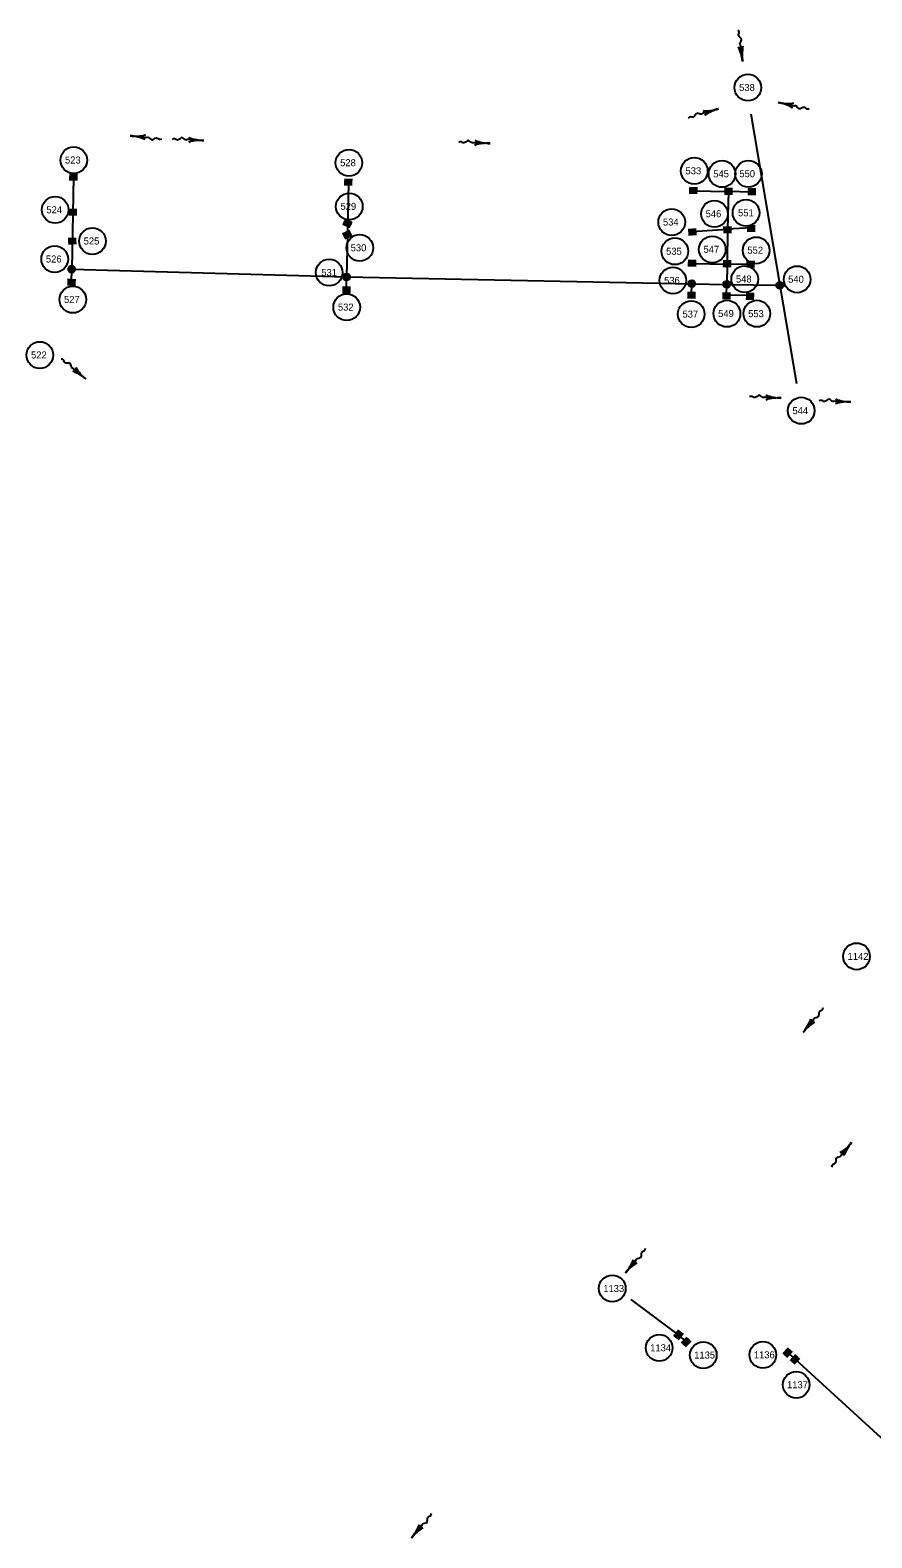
# Model space of a CAD drawing. Extents: x 594534 to 598564, y 225861 to 236229.
# Drawn here: x 595247 to 595967, y 230002 to 231290 of the extents above; entities that cross this region are included whole.
import ezdxf

# ---------------------------------------------------------------- set-up
doc = ezdxf.new("R2010")
doc.units = 0
for name, color, linetype in [('P_DRN_Flow', 7, 'Continuous'), ('P_DRN_Inlet', 7, 'Continuous'), ('P_DRN_SS_MH', 7, 'Continuous'), ('P_DRN_SS_UG', 7, 'Continuous'), ('P_DRN_Text', 7, 'Continuous')]:
    doc.layers.add(name, color=color, linetype=linetype)

msp = doc.modelspace()

# ---------------------------------------------------------------- linework, layer by layer
at = {"layer": 'P_DRN_Flow'}
for p, q in [((595856.3, 231263.7), (595854.4, 231277.7)), ((595886.7, 231228.6), (595900.6, 231225.8)), ((595835.6, 231223.2), (595822.1, 231219.1)), ((595332.9, 231200.1), (595347, 231198.6)), ((595395.8, 231196.1), (595381.7, 231196.8)), ((595640.4, 231193.6), (595626.3, 231194.2)), ((595295, 230992.3), (595284.1, 231001.3)), ((595889.1, 230976), (595875, 230976.6)), ((595948.6, 230972.6), (595934.5, 230973.2)), ((595908.1, 230434.1), (595917.1, 230444.9)), ((595949.5, 230339.6), (595940.4, 230328.8)), ((595756.3, 230228.4), (595765.3, 230239.2)), ((595573.3, 230001.9), (595582.4, 230012.7))]:
    msp.add_line(p, q, dxfattribs=at)
for points in [[(595852.6, 231276.1), (595855, 231273.2), (595856.6, 231276.6)], [(595899.7, 231228), (595896.1, 231226.7), (595898.9, 231224.1)], [(595823.9, 231217.6), (595826.4, 231220.4), (595822.7, 231221.4)], [(595345.9, 231200.8), (595342.5, 231199.1), (595345.5, 231196.8)], [(595382.9, 231194.7), (595386.2, 231196.5), (595383.1, 231198.7)], [(595627.5, 231192.2), (595630.8, 231194), (595627.7, 231196.2)], [(595283.8, 230998.9), (595287.6, 230998.4), (595286.4, 231002)], [(595876.3, 230974.5), (595879.6, 230976.4), (595876.4, 230978.5)], [(595935.8, 230971.2), (595939.1, 230973), (595935.9, 230975.2)], [(595914.8, 230445.2), (595914.2, 230441.5), (595917.8, 230442.6)], [(595942.8, 230328.5), (595943.3, 230332.2), (595939.7, 230331.1)], [(595762.9, 230239.5), (595762.4, 230235.8), (595766, 230236.9)], [(595580, 230012.9), (595579.4, 230009.2), (595583, 230010.4)]]:
    msp.add_lwpolyline(points, dxfattribs=at)
for centre, start, end in [((595814.7, 231258.1), 7.5832, 25.3455), ((595897.9, 231269.2), 169.8209, 187.5832), ((595895.2, 231269.7), 258.3474, 276.1098), ((595878.2, 231187.5), 60.5851, 78.3474), ((595823.3, 231263.3), 269.2685, 287.0308), ((595847.9, 231183.1), 107.0308, 124.7931), ((595337.3, 231241.8), 263.9732, 281.7355), ((595328.5, 231158.4), 66.2108, 83.9732), ((595393.9, 231154.2), 87.4555, 105.2178), ((595397.7, 231238), 249.6932, 267.4555), ((595638.5, 231151.7), 87.4555, 105.2178), ((595642.3, 231235.5), 249.6932, 267.4555), ((595268.3, 230959.9), 50.543, 68.3053), ((595321.6, 231024.7), 212.7806, 230.543), ((595887.3, 230934.1), 87.4555, 105.2178), ((595891, 231017.9), 249.6932, 267.4555), ((595946.8, 230930.7), 87.4555, 105.2178), ((595950.5, 231014.5), 249.6932, 267.4555), ((595875.9, 230461), 320.0425, 337.8048), ((595940.2, 230407.1), 122.2801, 140.0425), ((595917.4, 230366.6), 302.1583, 319.9206), ((595981.6, 230312.6), 139.9206, 157.6829), ((595724.1, 230255.3), 320.0425, 337.8048), ((595788.4, 230201.5), 122.2801, 140.0425), ((595541.1, 230028.8), 320.0425, 337.8048), ((595605.4, 229974.9), 122.2801, 140.0425)]:
    msp.add_arc(centre, 42, start, end, dxfattribs=at)
for points in [[(595854.4, 231277.7), (595854, 231278.4), (595855.4, 231282.2), (595852.7, 231285.8), (595853.3, 231288.8), (595852.4, 231290.4)], [(595822.1, 231219.1), (595821.4, 231218.6), (595817.4, 231219.3), (595814.3, 231216.1), (595811.3, 231216.1), (595809.8, 231215)], [(595900.6, 231225.8), (595901.4, 231225.9), (595904.5, 231223.3), (595908.8, 231224.7), (595911.4, 231223.2), (595913.2, 231223.5)], [(595347, 231198.6), (595347.8, 231198.9), (595351.2, 231196.6), (595355.3, 231198.4), (595358, 231197.2), (595359.8, 231197.6)], [(595381.7, 231196.8), (595380.9, 231196.5), (595377.4, 231198.5), (595373.4, 231196.5), (595370.6, 231197.6), (595368.8, 231197)], [(595626.3, 231194.2), (595625.5, 231194), (595622, 231196), (595617.9, 231194), (595615.2, 231195), (595613.4, 231194.5)], [(595284.1, 231001.3), (595283.3, 231001.6), (595281.7, 231005.3), (595277.2, 231006.1), (595275.7, 231008.6), (595273.9, 231009.3)], [(595875, 230976.6), (595874.2, 230976.3), (595870.7, 230978.4), (595866.7, 230976.3), (595863.9, 230977.4), (595862.2, 230976.9)], [(595934.5, 230973.2), (595933.7, 230973), (595930.2, 230975), (595926.2, 230973), (595923.4, 230974), (595921.7, 230973.5)], [(595917.1, 230444.9), (595917.4, 230445.7), (595921.2, 230447.3), (595922, 230451.7), (595924.5, 230453.3), (595925.2, 230455)], [(595940.4, 230328.8), (595940.1, 230328), (595936.3, 230326.4), (595935.5, 230322), (595932.9, 230320.4), (595932.3, 230318.7)], [(595765.3, 230239.2), (595765.6, 230240), (595769.4, 230241.6), (595770.2, 230246), (595772.7, 230247.6), (595773.4, 230249.3)], [(595582.4, 230012.7), (595582.6, 230013.5), (595586.4, 230015), (595587.2, 230019.5), (595589.7, 230021), (595590.4, 230022.8)]]:
    msp.add_spline(points, degree=3, dxfattribs=at)
at = {"layer": 'P_DRN_Inlet'}
for p, q in [((595280.8, 231164.6), (595287.7, 231164.5)), ((595280.8, 231163.7), (595287.7, 231163.6)), ((595280.8, 231162.8), (595287.7, 231162.7)), ((595280.9, 231167.3), (595287.8, 231167.2)), ((595280.9, 231166.4), (595287.7, 231166.3)), ((595280.9, 231165.5), (595287.7, 231165.4)), ((595522.8, 231162.6), (595515.9, 231162.8)), ((595522.7, 231161.7), (595515.9, 231161.9)), ((595522.7, 231160.8), (595515.8, 231161)), ((595522.7, 231159.9), (595515.8, 231160.1)), ((595522.7, 231159), (595515.8, 231159.2)), ((595522.7, 231158.1), (595515.8, 231158.3)), ((595810.6, 231151.3), (595817.5, 231151.1)), ((595810.7, 231154.9), (595817.6, 231154.7)), ((595810.7, 231154), (595817.6, 231153.8)), ((595810.7, 231153.1), (595817.6, 231152.9)), ((595810.7, 231152.2), (595817.5, 231152)), ((595810.8, 231155.8), (595817.6, 231155.6)), ((595840.7, 231155.1), (595847.6, 231155.1)), ((595840.7, 231154.2), (595847.6, 231154.2)), ((595840.7, 231153.3), (595847.6, 231153.3)), ((595840.7, 231152.4), (595847.6, 231152.4)), ((595840.7, 231151.5), (595847.6, 231151.5)), ((595840.7, 231150.6), (595847.6, 231150.6)), ((595860.7, 231153), (595867.6, 231152.9)), ((595860.7, 231152.1), (595867.6, 231152)), ((595860.7, 231151.2), (595867.6, 231151.1)), ((595860.7, 231150.3), (595867.5, 231150.2)), ((595860.8, 231154.8), (595867.7, 231154.7)), ((595860.8, 231153.9), (595867.6, 231153.8)), ((595280.3, 231136.4), (595287.2, 231136.3)), ((595280.4, 231137.3), (595287.2, 231137.2)), ((595280.3, 231135.5), (595287.2, 231135.4)), ((595280.3, 231134.6), (595287.2, 231134.5)), ((595280.3, 231133.7), (595287.2, 231133.6)), ((595280.3, 231132.8), (595287.2, 231132.7)), ((595520.7, 231121.7), (595514.5, 231124.7)), ((595521.1, 231122.5), (595514.9, 231125.5)), ((595521.5, 231123.3), (595515.3, 231126.3)), ((595521.9, 231124.1), (595515.7, 231127.1)), ((595522.3, 231124.9), (595516.1, 231128)), ((595522.7, 231125.7), (595516.5, 231128.8)), ((595860.2, 231123.3), (595867.1, 231123.2)), ((595279.8, 231112.3), (595286.6, 231112.7)), ((595279.8, 231111.4), (595286.7, 231111.8)), ((595279.9, 231110.5), (595286.7, 231110.9)), ((595514.4, 231116.2), (595520.7, 231119.1)), ((595514.8, 231115.4), (595521, 231118.3)), ((595515.2, 231114.6), (595521.4, 231117.5)), ((595515.5, 231113.8), (595521.8, 231116.7)), ((595515.9, 231113), (595522.2, 231115.8)), ((595516.3, 231112.2), (595522.5, 231115)), ((595809.8, 231120), (595816.6, 231120.5)), ((595809.8, 231119.1), (595816.7, 231119.6)), ((595809.9, 231118.2), (595816.8, 231118.7)), ((595810, 231117.3), (595816.8, 231117.8)), ((595810, 231116.4), (595816.9, 231116.9)), ((595810.1, 231115.5), (595817, 231116)), ((595839.8, 231121.9), (595846.7, 231122.2)), ((595839.9, 231121), (595846.8, 231121.3)), ((595839.9, 231120.1), (595846.8, 231120.4)), ((595840, 231119.2), (595846.8, 231119.5)), ((595840, 231118.3), (595846.9, 231118.6)), ((595840.1, 231117.4), (595846.9, 231117.7)), ((595860.1, 231118.8), (595867, 231118.7)), ((595860.2, 231122.4), (595867.1, 231122.3)), ((595860.2, 231121.5), (595867.1, 231121.4)), ((595860.2, 231120.6), (595867.1, 231120.5)), ((595860.2, 231119.7), (595867, 231119.6)), ((595279.9, 231109.6), (595286.8, 231110)), ((595280, 231108.7), (595286.8, 231109.1)), ((595280, 231107.8), (595286.9, 231108.2)), ((595809.6, 231091.1), (595816.5, 231090.9)), ((595809.6, 231090.2), (595816.5, 231090)), ((595809.6, 231089.3), (595816.5, 231089.1)), ((595809.7, 231093.8), (595816.6, 231093.6)), ((595809.7, 231092.9), (595816.6, 231092.7)), ((595809.7, 231092), (595816.5, 231091.8)), ((595839.5, 231088.7), (595846.4, 231088.6)), ((595839.6, 231093.2), (595846.5, 231093.1)), ((595839.6, 231092.3), (595846.5, 231092.2)), ((595839.6, 231091.4), (595846.5, 231091.3)), ((595839.6, 231090.5), (595846.5, 231090.4)), ((595839.6, 231089.6), (595846.4, 231089.5)), ((595859.6, 231091), (595866.5, 231090.8)), ((595859.6, 231090.1), (595866.5, 231089.9)), ((595859.6, 231089.2), (595866.5, 231089)), ((595859.6, 231088.3), (595866.4, 231088.2)), ((595859.7, 231092.8), (595866.6, 231092.6)), ((595859.7, 231091.9), (595866.5, 231091.7)), ((595279.2, 231073.9), (595286.1, 231073.5)), ((595279.2, 231073), (595286, 231072.6)), ((595279.3, 231075.7), (595286.2, 231075.3)), ((595279.3, 231074.8), (595286.1, 231074.4)), ((595279.4, 231077.5), (595286.3, 231077.1)), ((595279.4, 231076.6), (595286.2, 231076.2)), ((595514.2, 231069.9), (595521.1, 231069.7)), ((595514.2, 231069), (595521.1, 231068.8)), ((595514.2, 231068.1), (595521.1, 231067.9)), ((595514.2, 231067.2), (595521.1, 231067)), ((595514.2, 231066.3), (595521, 231066.1)), ((595514.3, 231070.8), (595521.1, 231070.6)), ((595809.1, 231061.8), (595816, 231061.7)), ((595809.2, 231066.3), (595816.1, 231066.2)), ((595809.2, 231065.4), (595816.1, 231065.3)), ((595809.2, 231064.5), (595816.1, 231064.4)), ((595809.2, 231063.6), (595816, 231063.5)), ((595809.2, 231062.7), (595816, 231062.6)), ((595839.1, 231064.8), (595846, 231064.7)), ((595839.1, 231063.9), (595846, 231063.8)), ((595839.1, 231063), (595846, 231062.9)), ((595839.1, 231062.1), (595846, 231062)), ((595839.1, 231061.2), (595845.9, 231061.1)), ((595839.2, 231065.7), (595846, 231065.6)), ((595859.1, 231060.8), (595866, 231060.7)), ((595859.2, 231065.3), (595866.1, 231065.2)), ((595859.2, 231064.4), (595866.1, 231064.3)), ((595859.2, 231063.5), (595866.1, 231063.4)), ((595859.2, 231062.6), (595866, 231062.5)), ((595859.2, 231061.7), (595866, 231061.6)), ((595797.6, 230174.1), (595801.8, 230179.5)), ((595798.3, 230173.5), (595802.5, 230178.9)), ((595799, 230173), (595803.3, 230178.4)), ((595799.7, 230172.4), (595804, 230177.8)), ((595800.4, 230171.9), (595804.7, 230177.3)), ((595801.1, 230171.3), (595805.4, 230176.7)), ((595804.2, 230168.5), (595809, 230173.4)), ((595804.8, 230167.9), (595809.6, 230172.8)), ((595805.5, 230167.2), (595810.3, 230172.2)), ((595806.1, 230166.6), (595810.9, 230171.6)), ((595806.8, 230166), (595811.6, 230170.9)), ((595807.4, 230165.4), (595812.2, 230170.3)), ((595890.9, 230159.3), (595895.5, 230164.3)), ((595891.5, 230158.7), (595896.2, 230163.7)), ((595892.2, 230158.1), (595896.9, 230163.1)), ((595892.9, 230157.5), (595897.5, 230162.5)), ((595893.5, 230156.8), (595898.2, 230161.9)), ((595894.2, 230156.2), (595898.9, 230161.3)), ((595897.1, 230153.5), (595901.8, 230158.6)), ((595897.8, 230152.9), (595902.5, 230158)), ((595898.4, 230152.3), (595903.1, 230157.3)), ((595899.1, 230151.7), (595903.8, 230156.7)), ((595899.8, 230151.1), (595904.4, 230156.1)), ((595900.4, 230150.5), (595905.1, 230155.5))]:
    msp.add_line(p, q, dxfattribs=at)
for points in [[(595283.3, 231164), (595285.3, 231164), (595285.3, 231166), (595283.3, 231166)], [(595520.3, 231161.4), (595518.3, 231161.5), (595518.2, 231159.5), (595520.2, 231159.4)], [(595813.1, 231152.5), (595815.1, 231152.4), (595815.2, 231154.4), (595813.2, 231154.5)], [(595843.2, 231151.9), (595845.2, 231151.9), (595845.2, 231153.9), (595843.2, 231153.9)], [(595863.1, 231151.5), (595865.1, 231151.5), (595865.2, 231153.5), (595863.2, 231153.5)], [(595282.7, 231134), (595284.7, 231134), (595284.8, 231136), (595282.8, 231136)], [(595520, 231125.7), (595518.2, 231126.6), (595517.3, 231124.8), (595519.1, 231123.9)], [(595282.4, 231109.2), (595284.4, 231109.3), (595284.3, 231111.3), (595282.3, 231111.2)], [(595518, 231114.3), (595519.8, 231115.1), (595519, 231117), (595517.2, 231116.1)], [(595812.4, 231116.9), (595814.4, 231117), (595814.3, 231119), (595812.3, 231118.9)], [(595842.4, 231118.7), (595844.4, 231118.8), (595844.3, 231120.8), (595842.3, 231120.7)], [(595862.6, 231120), (595864.6, 231120), (595864.7, 231122), (595862.7, 231122)], [(595812.1, 231090.5), (595814.1, 231090.4), (595814.1, 231092.4), (595812.1, 231092.5)], [(595842, 231089.9), (595844, 231089.9), (595844, 231091.9), (595842, 231091.9)], [(595862, 231089.5), (595864, 231089.5), (595864.1, 231091.5), (595862.1, 231091.5)], [(595281.7, 231074.1), (595283.7, 231074), (595283.8, 231076), (595281.8, 231076.1)], [(595516.6, 231067.5), (595518.6, 231067.4), (595518.7, 231069.4), (595516.7, 231069.5)], [(595811.6, 231063), (595813.6, 231063), (595813.6, 231065), (595811.6, 231065)], [(595841.5, 231062.4), (595843.5, 231062.4), (595843.6, 231064.4), (595841.6, 231064.4)], [(595861.6, 231062), (595863.6, 231062), (595863.6, 231064), (595861.6, 231064)], [(595801.6, 230174), (595802.9, 230175.6), (595801.3, 230176.8), (595800.1, 230175.2)], [(595808.2, 230168), (595809.6, 230169.4), (595808.2, 230170.8), (595806.8, 230169.4)], [(595894.9, 230158.9), (595896.3, 230160.3), (595894.8, 230161.7), (595893.5, 230160.2)], [(595901.2, 230153.1), (595902.5, 230154.6), (595901.1, 230155.9), (595899.7, 230154.5)]]:
    msp.add_lwpolyline(points, close=True, dxfattribs=at)
msp.add_lwpolyline([(595894.9, 230160.3), (595901.1, 230154.5)], dxfattribs=at)
at = {"layer": 'P_DRN_SS_MH'}
for centre, radius in [((595282.9, 231086.1), 2.98), ((595282.9, 231086.1), 2.4), ((595282.9, 231086.1), 1.8), ((595282.9, 231086.1), 1.2), ((595282.9, 231086.1), 0.6), ((595517.8, 231079.5), 2.98), ((595517.8, 231079.5), 2.4), ((595517.8, 231079.5), 1.8), ((595517.8, 231079.5), 1.2), ((595517.8, 231079.5), 0.6), ((595812.8, 231073.7), 2.98), ((595812.8, 231073.7), 2.4), ((595812.8, 231073.7), 1.8), ((595812.8, 231073.7), 1.2), ((595812.8, 231073.7), 0.6), ((595842.7, 231073.1), 2.98), ((595842.7, 231073.1), 2.4), ((595842.7, 231073.1), 1.8), ((595842.7, 231073.1), 1.2), ((595842.7, 231073.1), 0.6), ((595888.1, 231072.3), 2.98), ((595888.1, 231072.3), 2.4), ((595888.1, 231072.3), 1.8), ((595888.1, 231072.3), 1.2), ((595888.1, 231072.3), 0.6)]:
    msp.add_circle(centre, radius, dxfattribs=at)
at = {"layer": 'P_DRN_SS_UG'}
for p, q in [((595863.3, 231218.9), (595888.1, 231072.3)), ((595284.3, 231165), (595282.9, 231086.1)), ((595814.1, 231153), (595844.2, 231152.4)), ((595844.2, 231152.4), (595843.4, 231120.2)), ((595864.2, 231152), (595844.2, 231152.4)), ((595813.3, 231118.4), (595843.4, 231120.2)), ((595843.4, 231120.2), (595843, 231090.4)), ((595863.6, 231121.5), (595843.4, 231120.2)), ((595282.7, 231075.1), (595282.9, 231086.1)), ((595282.9, 231086.1), (595517.8, 231079.5)), ((595813.1, 231091), (595843, 231090.4)), ((595843, 231090.4), (595842.7, 231073.1)), ((595863.1, 231090), (595843, 231090.4)), ((595517.6, 231068.5), (595517.8, 231079.5)), ((595517.8, 231079.5), (595812.8, 231073.7)), ((595812.6, 231064.4), (595812.8, 231073.7)), ((595812.8, 231073.7), (595842.7, 231073.1)), ((595842.6, 231063.8), (595842.7, 231073.1)), ((595842.7, 231073.1), (595888.1, 231072.3)), ((595888.1, 231072.3), (595902.3, 230988.5)), ((595862.6, 231063.5), (595842.6, 231063.8)), ((595801.5, 230175.4), (595761, 230205.6)), ((595808.2, 230169.4), (595801.5, 230175.4)), ((595894.9, 230160.3), (595901.1, 230154.5)), ((595901.1, 230154.5), (595987.9, 230075.5))]:
    msp.add_line(p, q, dxfattribs=at)
msp.add_lwpolyline([(595519.3, 231160.5), (595518.5, 231115.6), (595517.8, 231079.5)], dxfattribs=at)
at = {"layer": 'P_DRN_Text'}
for centre in [(595860.8, 231241.3), (595284.6, 231179.3), (595519.8, 231177), (595815, 231170.1), (595838.7, 231167.5), (595861.3, 231167.6), (595520.1, 231139.7), (595268.7, 231136.8), (595795.7, 231126.3), (595832.2, 231133.4), (595859.2, 231134.3), (595300.6, 231110.1), (595529.1, 231104.3), (595798.4, 231101.4), (595830.4, 231103), (595867.9, 231102.2), (595268.3, 231094.7), (595502.9, 231083.2), (595796.7, 231076.4), (595858.1, 231077.6), (595902.9, 231077.4), (595283.8, 231060.1), (595517.9, 231053.6), (595812.4, 231047.7), (595842.9, 231048.1), (595868.5, 231048.1), (595255.6, 231012.7), (595906.4, 230965.2), (595953.7, 230498.8), (595744.9, 230215), (595785, 230164.2), (595822.7, 230158), (595873.6, 230158.2), (595902.1, 230132.6)]:
    msp.add_circle(centre, 11.4, dxfattribs=at)

# ---------------------------------------------------------------- texts
for s, p in [('538', (595853.3, 231238.4)), ('523', (595277.1, 231176.4)), ('528', (595512.3, 231174.1)), ('533', (595807.5, 231167.2)), ('545', (595831.2, 231164.6)), ('550', (595853.5, 231164.7)), ('524', (595261.2, 231133.9)), ('529', (595512.6, 231136.8)), ('546', (595824.7, 231130.5)), ('551', (595852.4, 231131.3)), ('534', (595788.2, 231123.4)), ('525', (595293.1, 231107.2)), ('526', (595260.8, 231091.8)), ('530', (595521.3, 231101.4)), ('535', (595790.9, 231098.4)), ('547', (595822.9, 231100.1)), ('552', (595860.4, 231099.3)), ('531', (595496.2, 231080.3)), ('536', (595789.2, 231073.5)), ('548', (595850.6, 231074.7)), ('540', (595895.2, 231074.5)), ('527', (595276.3, 231057.2)), ('532', (595510.4, 231050.7)), ('537', (595804.9, 231044.7)), ('549', (595835.4, 231045.2)), ('553', (595861, 231045.1)), ('522', (595248.1, 231009.8)), ('544', (595898.9, 230962.2)), ('1142', (595946, 230495.8)), ('1133', (595737.2, 230212)), ('1134', (595777.3, 230161.3)), ('1135', (595814.9, 230155.1)), ('1136', (595865.9, 230155.3)), ('1137', (595894.3, 230129.7))]:
    msp.add_text(s, height=6, dxfattribs=at).set_placement(p)

doc.saveas('drawing.dxf')
